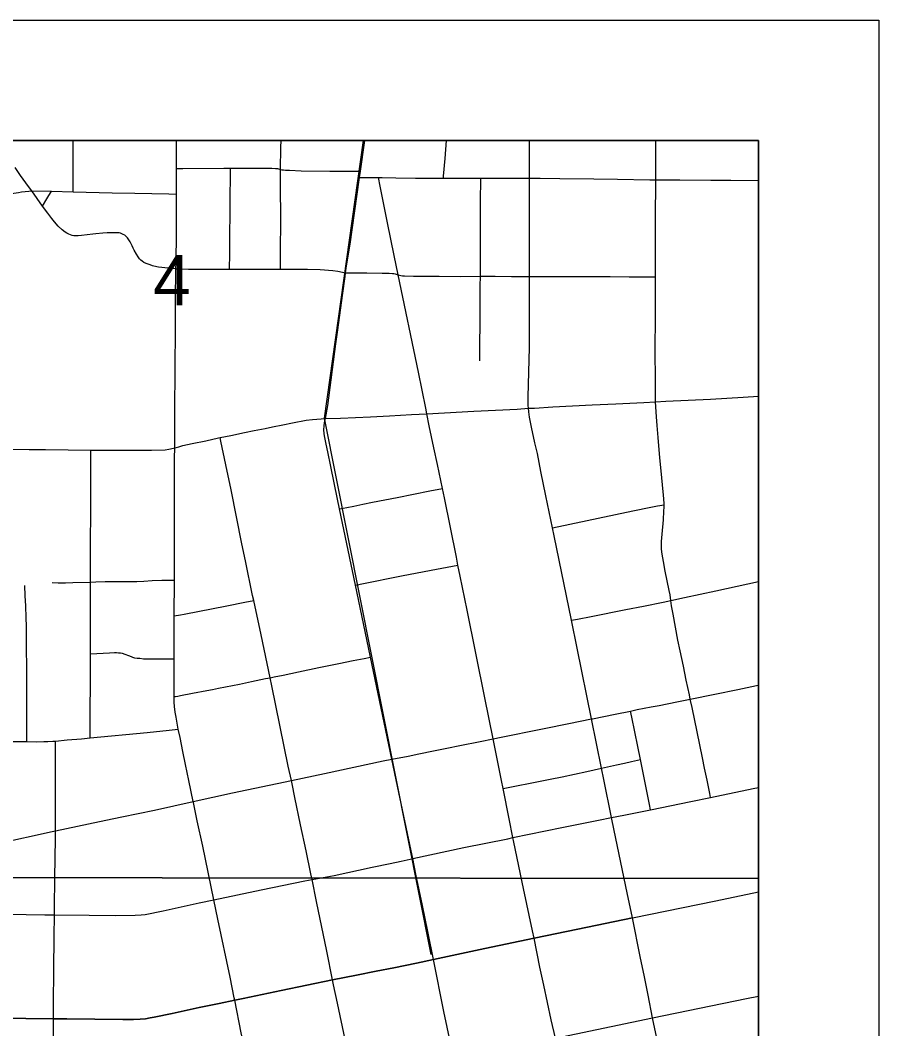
# Model space of a CAD drawing. Extents: x 0 to 34, y 0 to 22.
# Drawn here: x 8.286 to 9, y 20.161 to 21 of the extents above; entities that cross this region are included whole.
import ezdxf

# ---------------------------------------------------------------- set-up
doc = ezdxf.new("R2010")
doc.units = 0
for name, color, linetype in [('GM_X_City_Street', 7, 'Continuous'), ('GM_X_County_Road', 7, 'Continuous'), ('GM_X_Rail_Line', 7, 'Continuous'), ('GM_X_Section_Text', 7, 'Continuous'), ('GM_X_State_Route', 7, 'Continuous'), ('GM_X_Township_Road', 7, 'Continuous'), ('GM_X_Unincorporated', 7, 'Continuous'), ('SH_Data', 7, 'Continuous')]:
    doc.layers.add(name, color=color, linetype=linetype)

msp = doc.modelspace()

# ---------------------------------------------------------------- linework, layer by layer
at = {"layer": 'GM_X_City_Street'}
for points in [[(8.33031, 20.85723), (8.33032, 20.88691), (8.33032, 20.89996)], [(8.43013, 20.35007), (8.42648, 20.36751), (8.4237, 20.38082), (8.42151, 20.39169), (8.41914, 20.40339), (8.41768, 20.41038), (8.41669, 20.41511), (8.41578, 20.4201), (8.41501, 20.42446), (8.41446, 20.42904), (8.41431, 20.43279), (8.41429, 20.43736), (8.41418, 20.45868), (8.41419, 20.46877), (8.41419, 20.48821), (8.41426, 20.50453), (8.41438, 20.53424), (8.4144, 20.53833), (8.4144, 20.56296), (8.41454, 20.57978), (8.41454, 20.59348), (8.41462, 20.60812), (8.41455, 20.61864), (8.41462, 20.63566), (8.4149, 20.64422), (8.41489, 20.67671), (8.41496, 20.7077), (8.41531, 20.74537), (8.41538, 20.76696), (8.41573, 20.79312), (8.4158, 20.798), (8.41606, 20.82281), (8.41604, 20.84142), (8.41606, 20.85537), (8.41608, 20.86932), (8.41612, 20.8766), (8.41623, 20.89996)], [(8.50267, 20.87586), (8.50301, 20.89406), (8.50306, 20.89996)], [(8.63804, 20.86852), (8.63817, 20.8701), (8.63938, 20.88496), (8.6406, 20.89996)], [(8.86001, 20.35342), (8.85939, 20.35664), (8.85725, 20.36783), (8.85515, 20.37773), (8.85345, 20.38652), (8.84893, 20.40807), (8.84471, 20.42824), (8.84321, 20.43528), (8.8425, 20.43878), (8.83993, 20.45107), (8.8375, 20.46272), (8.83482, 20.4755), (8.83298, 20.48432), (8.82895, 20.50591), (8.82776, 20.51294), (8.82713, 20.51733), (8.82645, 20.52199), (8.8257, 20.52572), (8.82241, 20.54162), (8.82087, 20.54984), (8.81992, 20.55591), (8.81944, 20.55995), (8.8193, 20.56292), (8.8193, 20.56627), (8.81982, 20.57252), (8.82093, 20.58443), (8.82135, 20.59162), (8.82159, 20.59483), (8.82156, 20.59694), (8.82159, 20.59769), (8.82119, 20.60174), (8.82092, 20.60498), (8.82004, 20.61354), (8.81902, 20.62515), (8.81808, 20.63589), (8.81669, 20.65278), (8.81577, 20.6628), (8.81518, 20.67006), (8.81431, 20.68247), (8.81429, 20.68744), (8.81426, 20.6991), (8.81418, 20.72625), (8.81434, 20.75248), (8.8143, 20.78644), (8.81431, 20.80361), (8.81444, 20.8342), (8.81455, 20.86727), (8.81461, 20.87592), (8.81457, 20.89996)], [(8.41573, 20.79312), (8.40928, 20.79379), (8.40127, 20.79462), (8.39973, 20.79486), (8.39633, 20.79569), (8.39432, 20.79636), (8.39249, 20.797), (8.39095, 20.7976), (8.38913, 20.79851), (8.3877, 20.79947), (8.38661, 20.80042), (8.38551, 20.80158), (8.38422, 20.80323), (8.3829, 20.80538), (8.38102, 20.80862), (8.38018, 20.81034), (8.37918, 20.81239), (8.37763, 20.81554), (8.37713, 20.81653), (8.376, 20.81815), (8.37532, 20.81901), (8.37432, 20.82005), (8.37312, 20.82102), (8.37189, 20.82173), (8.37059, 20.82236), (8.36953, 20.82272), (8.36839, 20.823), (8.36735, 20.82312), (8.36515, 20.8232), (8.3631, 20.82316), (8.36122, 20.82315), (8.35864, 20.82301), (8.35502, 20.82273), (8.34915, 20.8222), (8.34663, 20.82194), (8.33726, 20.82093), (8.33433, 20.82061), (8.332, 20.82063), (8.3307, 20.82068), (8.32949, 20.82087), (8.328, 20.82135), (8.32661, 20.82189), (8.32512, 20.82274), (8.32363, 20.82359), (8.32107, 20.82551), (8.31783, 20.82875), (8.31463, 20.83233), (8.31242, 20.83508), (8.30909, 20.83938), (8.30486, 20.84535), (8.29586, 20.85805), (8.29316, 20.86148), (8.28647, 20.87073), (8.28211, 20.87732)], [(8.41612, 20.8766), (8.42149, 20.87662), (8.45547, 20.87675), (8.46118, 20.87677), (8.48635, 20.87687), (8.4953, 20.87677), (8.49848, 20.87664), (8.50021, 20.87647), (8.50165, 20.87612), (8.50267, 20.87586), (8.50378, 20.87559), (8.50503, 20.87534), (8.50684, 20.87516), (8.50998, 20.87508), (8.51985, 20.87468), (8.54363, 20.87442), (8.56164, 20.87447), (8.56904, 20.87449)], [(8.46026, 20.79286), (8.46052, 20.80574), (8.4606, 20.81165), (8.46049, 20.81469), (8.46118, 20.87677)], [(8.50266, 20.79278), (8.50263, 20.79616), (8.50257, 20.80269), (8.50251, 20.80968), (8.50276, 20.83152), (8.50251, 20.86546), (8.50265, 20.87437), (8.50267, 20.87586)], [(8.56826, 20.86902), (8.57654, 20.86902), (8.58408, 20.86901), (8.5872, 20.86901), (8.59854, 20.86884), (8.61495, 20.86867), (8.62799, 20.86867), (8.63804, 20.86852), (8.6395, 20.8685), (8.65438, 20.86849), (8.66915, 20.86863), (8.67232, 20.86866), (8.70963, 20.86849), (8.71836, 20.86848), (8.73494, 20.8683), (8.76304, 20.86796), (8.78267, 20.86779), (8.80958, 20.86727), (8.81455, 20.86727), (8.83446, 20.86727), (8.86036, 20.86692), (8.87711, 20.86675), (8.9, 20.86674)], [(8.6242, 20.67255), (8.6233, 20.67717), (8.61724, 20.70732), (8.60041, 20.78827), (8.59709, 20.80416), (8.59153, 20.8315), (8.58548, 20.86197), (8.58408, 20.86901)], [(8.66843, 20.71661), (8.66861, 20.7612), (8.66873, 20.77861), (8.66876, 20.78695), (8.66883, 20.79763), (8.66898, 20.82588), (8.66898, 20.85419), (8.66909, 20.86304), (8.66915, 20.86863)], [(8.24535, 20.84633), (8.24959, 20.84796), (8.25348, 20.84945), (8.2572, 20.85077), (8.25987, 20.8517), (8.26461, 20.85299), (8.26974, 20.85414), (8.27704, 20.85545), (8.28474, 20.8567), (8.28737, 20.85706), (8.29342, 20.85778), (8.29586, 20.85805)], [(8.29586, 20.85805), (8.31221, 20.85766), (8.33031, 20.85723), (8.36272, 20.85647), (8.38158, 20.85607), (8.40987, 20.8555), (8.41606, 20.85537)], [(8.30486, 20.84535), (8.30849, 20.85141), (8.31221, 20.85766)], [(8.41573, 20.79312), (8.42007, 20.79301), (8.42609, 20.79286), (8.46026, 20.79286), (8.46343, 20.79285), (8.50266, 20.79278), (8.52494, 20.79273), (8.53569, 20.79261), (8.54625, 20.79165), (8.55041, 20.79109), (8.55675, 20.78988)], [(8.55675, 20.78988), (8.56254, 20.78983), (8.57451, 20.78974), (8.58721, 20.78957), (8.59303, 20.78947), (8.5956, 20.78934), (8.59683, 20.78918), (8.59801, 20.7889), (8.60041, 20.78827), (8.60262, 20.78769), (8.60407, 20.78738), (8.60563, 20.78726), (8.61311, 20.78705), (8.63448, 20.78696), (8.65233, 20.78689), (8.66876, 20.78695), (8.68116, 20.78698), (8.69457, 20.78686), (8.70256, 20.78678), (8.70957, 20.78679), (8.71578, 20.78668), (8.74114, 20.78677), (8.75851, 20.78667), (8.77656, 20.78667), (8.79245, 20.78657), (8.81129, 20.78646), (8.8143, 20.78644)], [(8.71336, 20.23643), (8.71213, 20.2424), (8.70468, 20.27777), (8.69661, 20.3164), (8.69587, 20.32008), (8.69275, 20.33563), (8.68772, 20.36081), (8.68632, 20.36759), (8.67934, 20.4023), (8.6725, 20.43626), (8.65778, 20.50928), (8.65202, 20.53754), (8.65015, 20.54655), (8.64882, 20.55326), (8.63894, 20.60267), (8.63727, 20.61048), (8.63301, 20.63028), (8.63012, 20.64413), (8.62625, 20.66264), (8.6242, 20.67255)], [(8.54572, 20.20166), (8.541, 20.22551), (8.53252, 20.26685), (8.52884, 20.2853), (8.52789, 20.29003), (8.52387, 20.30914), (8.51928, 20.33071), (8.51454, 20.35348), (8.51231, 20.36465), (8.51174, 20.36748), (8.50909, 20.37934), (8.49531, 20.44628), (8.49391, 20.45299), (8.48645, 20.4887), (8.48031, 20.51725), (8.47942, 20.52137), (8.47356, 20.55015), (8.47055, 20.56429), (8.4615, 20.60942), (8.45715, 20.63018), (8.45313, 20.64984), (8.45253, 20.65279)], [(8.34451, 20.40294), (8.34435, 20.41884), (8.3447, 20.45509), (8.34467, 20.47287), (8.34459, 20.53128), (8.34458, 20.53255), (8.34471, 20.56077), (8.34487, 20.59509), (8.3449, 20.61659), (8.34491, 20.62157), (8.34494, 20.6386), (8.34494, 20.64226)], [(8.55175, 20.59346), (8.55771, 20.59468), (8.56347, 20.59586), (8.5711, 20.59742), (8.57922, 20.59908), (8.5996, 20.60307), (8.61308, 20.60571), (8.62666, 20.60836), (8.63727, 20.61048)], [(8.72869, 20.57772), (8.79549, 20.59178), (8.81039, 20.5949), (8.81591, 20.59591), (8.82156, 20.59694)], [(8.56497, 20.53009), (8.57175, 20.53145), (8.58136, 20.53338), (8.59212, 20.53554), (8.60332, 20.53779), (8.62779, 20.54243), (8.65015, 20.54655)], [(8.29164, 20.39987), (8.29168, 20.41339), (8.29174, 20.43325), (8.2918, 20.45598), (8.29142, 20.48327), (8.29142, 20.49581), (8.29117, 20.50288), (8.29081, 20.51281), (8.29043, 20.52113), (8.29021, 20.52977)], [(8.31284, 20.53227), (8.31773, 20.53208), (8.3238, 20.53203), (8.32985, 20.53214), (8.34458, 20.53255), (8.34922, 20.53291), (8.3569, 20.53307), (8.36218, 20.53302), (8.38321, 20.53314), (8.38903, 20.53326), (8.39593, 20.53378), (8.40405, 20.53429), (8.40909, 20.53426), (8.41438, 20.53424)], [(8.74451, 20.50082), (8.7494, 20.50174), (8.76101, 20.50395), (8.78982, 20.50967), (8.80438, 20.51261), (8.82084, 20.51599), (8.82713, 20.51733), (8.83848, 20.51966), (8.86454, 20.5252), (8.9, 20.53302)], [(8.41426, 20.50453), (8.41944, 20.50545), (8.42241, 20.50598), (8.45812, 20.51287), (8.47298, 20.51581), (8.48031, 20.51725)], [(8.34467, 20.47287), (8.36054, 20.47371), (8.36474, 20.47393), (8.3664, 20.47394), (8.36802, 20.47381), (8.3697, 20.47362), (8.37093, 20.47343), (8.37843, 20.47057), (8.3795, 20.47016), (8.38117, 20.46968), (8.38355, 20.46936), (8.38568, 20.46917), (8.38883, 20.46889), (8.39987, 20.46877), (8.40799, 20.46877), (8.41419, 20.46877)], [(8.41429, 20.43736), (8.41525, 20.43751), (8.41721, 20.43782), (8.41941, 20.43824), (8.42958, 20.44026), (8.44129, 20.44253), (8.44604, 20.44336), (8.4512, 20.44443), (8.46843, 20.44773), (8.47854, 20.44999), (8.49018, 20.45226), (8.49391, 20.45299), (8.49741, 20.45367), (8.50489, 20.4552), (8.51757, 20.45795), (8.53454, 20.46144), (8.55121, 20.4648), (8.56296, 20.46731), (8.57208, 20.46907), (8.57751, 20.47012)], [(8.81029, 20.34324), (8.80943, 20.3475), (8.8018, 20.38501), (8.7996, 20.39583), (8.79456, 20.42016), (8.79348, 20.42536)], [(8.27809, 20.3999), (8.29164, 20.39987), (8.29997, 20.39985), (8.30575, 20.39996), (8.30917, 20.39996), (8.31328, 20.40022), (8.31546, 20.40039), (8.32537, 20.40128), (8.33732, 20.4023), (8.34451, 20.40294), (8.39179, 20.40747), (8.41004, 20.40952), (8.41768, 20.41038)], [(8.31399, 20.1694), (8.31399, 20.17555), (8.314, 20.18176), (8.31426, 20.20999), (8.31436, 20.23753), (8.31465, 20.25583), (8.31474, 20.26163), (8.31502, 20.28648), (8.31559, 20.31934), (8.31564, 20.32565), (8.31569, 20.33153), (8.3155, 20.34604), (8.3157, 20.38513), (8.31551, 20.39676), (8.31546, 20.40039)], [(8.68772, 20.36081), (8.69743, 20.36278), (8.71167, 20.36561), (8.72691, 20.36865), (8.73667, 20.3706), (8.75718, 20.37508), (8.76951, 20.37777), (8.78198, 20.38048), (8.78864, 20.38193), (8.79437, 20.38327), (8.8018, 20.38501)], [(8.73114, 20.15326), (8.72754, 20.16859), (8.72144, 20.19739), (8.71832, 20.21226), (8.71336, 20.23643)], [(8.56262, 20.12181), (8.54997, 20.18237), (8.54663, 20.19753), (8.54572, 20.20166)], [(8.81194, 20.17023), (8.88991, 20.1861), (8.9, 20.18822)]]:
    msp.add_lwpolyline(points, dxfattribs=at)
at = {"layer": 'GM_X_County_Road'}
for p, q in [((8.56904, 20.87449), (8.57266, 20.89996)), ((8.56826, 20.86902), (8.56904, 20.87449)), ((8.56497, 20.53009), (8.55175, 20.59346)), ((8.59529, 20.38522), (8.57751, 20.47012)), ((8.76951, 20.37777), (8.76118, 20.4188)), ((8.45173, 20.18217), (8.46452, 20.18481)), ((8.73114, 20.15326), (8.81194, 20.17023))]:
    msp.add_line(p, q, dxfattribs=at)
for points in [[(8.70963, 20.86849), (8.70961, 20.87474), (8.70961, 20.88684), (8.70961, 20.89996)], [(8.55675, 20.78988), (8.55724, 20.79356), (8.5604, 20.81378), (8.56826, 20.86902)], [(8.70957, 20.78679), (8.7096, 20.80014), (8.7097, 20.81085), (8.70962, 20.84893), (8.70963, 20.86849)], [(8.53996, 20.66874), (8.54188, 20.67949), (8.54859, 20.73074), (8.55023, 20.74241), (8.55453, 20.773), (8.55634, 20.78675), (8.55675, 20.78988)], [(8.70869, 20.67711), (8.7086, 20.67938), (8.70862, 20.68222), (8.70862, 20.68666), (8.70956, 20.72783), (8.70952, 20.7604), (8.70956, 20.77789), (8.70957, 20.78583), (8.70957, 20.78679)], [(8.72869, 20.57772), (8.72315, 20.60433), (8.71909, 20.62457), (8.71632, 20.63956), (8.71399, 20.64854), (8.7114, 20.66144), (8.70973, 20.66978), (8.70901, 20.67409), (8.70869, 20.67711)], [(8.55175, 20.59346), (8.55006, 20.60154), (8.54442, 20.62863), (8.54184, 20.64101), (8.54054, 20.64722), (8.53944, 20.65279), (8.53891, 20.65586), (8.53868, 20.65951), (8.53886, 20.66241), (8.53927, 20.66543), (8.53996, 20.66874)], [(8.74451, 20.50082), (8.73009, 20.57101), (8.72869, 20.57772)], [(8.57751, 20.47012), (8.57024, 20.50478), (8.56497, 20.53009)], [(8.76118, 20.4188), (8.74925, 20.47758), (8.74451, 20.50082)], [(8.84321, 20.43528), (8.86375, 20.43939), (8.88271, 20.44334), (8.89841, 20.44659), (8.9, 20.44692)], [(8.79348, 20.42536), (8.79911, 20.42653), (8.81086, 20.42879), (8.81731, 20.43), (8.8322, 20.43304), (8.84321, 20.43528)], [(8.76118, 20.4188), (8.76209, 20.41897), (8.78076, 20.42273), (8.79348, 20.42536)], [(8.67934, 20.4023), (8.6861, 20.40364), (8.69587, 20.40562), (8.70944, 20.4083), (8.72189, 20.41071), (8.74239, 20.41495), (8.76118, 20.4188)], [(8.59529, 20.38522), (8.60887, 20.38782), (8.61768, 20.38977), (8.62974, 20.39222), (8.64098, 20.39446), (8.65173, 20.39658), (8.66871, 20.40011), (8.67934, 20.4023)], [(8.51174, 20.36748), (8.53931, 20.37326), (8.58801, 20.3839), (8.59529, 20.38522)], [(8.6125, 20.3027), (8.61117, 20.30908), (8.60001, 20.36276), (8.59529, 20.38522)], [(8.77785, 20.33677), (8.77141, 20.36843), (8.76951, 20.37777)], [(8.43013, 20.35007), (8.46272, 20.35721), (8.51174, 20.36748)], [(8.86001, 20.35342), (8.89559, 20.36093), (8.9, 20.36186)], [(8.81029, 20.34324), (8.84362, 20.34997), (8.86001, 20.35342)], [(8.31564, 20.32565), (8.35202, 20.33355), (8.36415, 20.33601), (8.37085, 20.33727), (8.39781, 20.343), (8.43013, 20.35007)], [(8.44721, 20.26831), (8.43798, 20.31285), (8.43345, 20.3341), (8.43029, 20.34929), (8.43013, 20.35007)], [(8.69587, 20.32008), (8.73636, 20.32845), (8.7669, 20.33465), (8.77785, 20.33677)], [(8.77785, 20.33677), (8.78796, 20.33873), (8.81029, 20.34324)], [(8.79527, 20.25346), (8.79087, 20.27424), (8.78004, 20.32583), (8.77785, 20.33677)], [(8.20969, 20.30288), (8.21616, 20.30422), (8.26742, 20.31518), (8.31271, 20.32502), (8.31564, 20.32565)], [(8.6125, 20.3027), (8.65505, 20.3117), (8.69166, 20.31917), (8.69587, 20.32008)], [(8.52884, 20.2853), (8.54724, 20.28864), (8.57893, 20.29551), (8.59389, 20.2986), (8.60302, 20.30051), (8.61049, 20.30221), (8.6125, 20.3027)], [(8.62971, 20.21855), (8.62499, 20.24208), (8.62066, 20.26346), (8.61523, 20.28957), (8.6125, 20.3027)], [(8.44721, 20.26831), (8.48663, 20.27663), (8.52293, 20.28423), (8.52884, 20.2853)], [(8.79527, 20.25346), (8.8645, 20.26743), (8.9, 20.27487)], [(8.31465, 20.25583), (8.34368, 20.25543), (8.36537, 20.25522), (8.38175, 20.25545), (8.38667, 20.25577), (8.39003, 20.2562), (8.40512, 20.25914), (8.43507, 20.26574), (8.44721, 20.26831)], [(8.46452, 20.18481), (8.46411, 20.18682), (8.46067, 20.20384), (8.45055, 20.25217), (8.44721, 20.26831)], [(8.14257, 20.25707), (8.14758, 20.25709), (8.17223, 20.25716), (8.2124, 20.25683), (8.24485, 20.25661), (8.27562, 20.25635), (8.30662, 20.25593), (8.31465, 20.25583)], [(8.71336, 20.23643), (8.74978, 20.24399), (8.79527, 20.25346)], [(8.62971, 20.21855), (8.67255, 20.22796), (8.71336, 20.23643)], [(8.54572, 20.20166), (8.56572, 20.20577), (8.58217, 20.20888), (8.59689, 20.21177), (8.61569, 20.21559), (8.62971, 20.21855)], [(8.64675, 20.13558), (8.64577, 20.14013), (8.63846, 20.17542), (8.62971, 20.21855)], [(8.46452, 20.18481), (8.47171, 20.1863), (8.50308, 20.19289), (8.54572, 20.20166)], [(8.31399, 20.1694), (8.32505, 20.16925), (8.37153, 20.16876), (8.38051, 20.16883), (8.38582, 20.16896), (8.39044, 20.16944), (8.3944, 20.17005), (8.39759, 20.17073), (8.4125, 20.17386), (8.43501, 20.17872), (8.45173, 20.18217)], [(8.4818, 20.10167), (8.47535, 20.13279), (8.46991, 20.15772), (8.46452, 20.18481)], [(8.25454, 20.07875), (8.26505, 20.08873), (8.30472, 20.1262), (8.30612, 20.12772), (8.30764, 20.12933), (8.30915, 20.13101), (8.31007, 20.13236), (8.31083, 20.1336), (8.31153, 20.13479), (8.31212, 20.13609), (8.31272, 20.1377), (8.31315, 20.13937), (8.31342, 20.14154), (8.31364, 20.1437), (8.31369, 20.14564), (8.3138, 20.14737), (8.31374, 20.15083), (8.31379, 20.15482), (8.31399, 20.1694)], [(8.25603, 20.17457), (8.25817, 20.17341), (8.26112, 20.17212), (8.26449, 20.17096), (8.26754, 20.17028), (8.27136, 20.16988), (8.29082, 20.16973), (8.31399, 20.1694)]]:
    msp.add_lwpolyline(points, dxfattribs=at)
at = {"layer": 'GM_X_Rail_Line'}
msp.add_lwpolyline([(8.57139, 20.89996), (8.53897, 20.66884), (8.62772, 20.22287)], dxfattribs=at)
at = {"layer": 'GM_X_State_Route'}
msp.add_line((8.46452, 20.18481), (8.45173, 20.18217), dxfattribs=at)
for points in [[(8.9, 19.05919), (8.9, 20.89996), (6.88573, 20.89996)], [(8.79527, 20.25346), (8.74978, 20.24399), (8.71336, 20.23643)], [(8.83601, 19.91254), (8.83597, 19.91666), (8.83581, 19.92344), (8.83565, 19.92703), (8.83193, 20.00245), (8.82983, 20.05801), (8.82799, 20.08801), (8.82793, 20.08901), (8.82741, 20.0936), (8.82685, 20.09831), (8.82581, 20.10433), (8.82497, 20.10867), (8.82204, 20.12219), (8.81194, 20.17023), (8.80825, 20.18912), (8.80509, 20.20424), (8.80158, 20.22103), (8.79527, 20.25346)], [(8.71336, 20.23643), (8.67255, 20.22796), (8.62971, 20.21855)], [(8.62971, 20.21855), (8.61569, 20.21559), (8.59689, 20.21177), (8.58217, 20.20888), (8.56572, 20.20577), (8.54572, 20.20166)], [(8.54572, 20.20166), (8.50308, 20.19289), (8.47171, 20.1863), (8.46452, 20.18481)], [(8.45173, 20.18217), (8.43501, 20.17872), (8.4125, 20.17386), (8.39759, 20.17073), (8.3944, 20.17005), (8.39044, 20.16944), (8.38582, 20.16896), (8.38051, 20.16883), (8.37153, 20.16876), (8.32505, 20.16925), (8.31399, 20.1694)], [(8.31399, 20.1694), (8.29082, 20.16973), (8.27136, 20.16988), (8.26754, 20.17028), (8.26449, 20.17096), (8.26112, 20.17212), (8.25817, 20.17341), (8.25603, 20.17457)]]:
    msp.add_lwpolyline(points, dxfattribs=at)
at = {"layer": 'GM_X_Township_Road'}
msp.add_line((8.88729, 20.68641), (8.9, 20.68714), dxfattribs=at)
for points in [[(8.9, 17.26338), (8.9, 20.89996), (5.78179, 20.89996)], [(8.70869, 20.67711), (8.71382, 20.67738), (8.7291, 20.67835), (8.76176, 20.67993), (8.78148, 20.68084), (8.80454, 20.68194), (8.81431, 20.68247)], [(8.81431, 20.68247), (8.82307, 20.68294), (8.85998, 20.68485), (8.88729, 20.68641)], [(8.53996, 20.66874), (8.5525, 20.66884), (8.57751, 20.67005), (8.59322, 20.67074), (8.61155, 20.67184), (8.6242, 20.67255)], [(8.6242, 20.67255), (8.63906, 20.67337), (8.66324, 20.67461), (8.69936, 20.67655), (8.70869, 20.67711)], [(8.45253, 20.65279), (8.46145, 20.6546), (8.4726, 20.6569), (8.48086, 20.65853), (8.48978, 20.66032), (8.49603, 20.66158), (8.50451, 20.66336), (8.51269, 20.665), (8.52385, 20.66715), (8.52916, 20.66787), (8.53996, 20.66874)], [(8.4149, 20.64422), (8.41816, 20.64516), (8.42151, 20.64606), (8.42925, 20.64784), (8.44055, 20.65014), (8.45113, 20.6525), (8.45253, 20.65279)], [(8.22036, 20.64359), (8.22445, 20.64357), (8.24519, 20.64342), (8.26091, 20.64326), (8.29363, 20.64297), (8.30735, 20.64273), (8.34494, 20.64226)], [(8.34494, 20.64226), (8.36254, 20.64221), (8.39526, 20.64227), (8.40679, 20.64257), (8.40984, 20.64301), (8.41356, 20.6439), (8.4149, 20.64422)]]:
    msp.add_lwpolyline(points, dxfattribs=at)
at = {"layer": 'GM_X_Unincorporated'}
for points in [[(8.9, 20.28618), (8.9, 20.89996), (7.91044, 20.89996), (7.90836, 20.28708)], [(8.9, 19.27567), (8.9, 20.28618), (7.90836, 20.28708), (7.90787, 19.27209)]]:
    msp.add_lwpolyline(points, close=True, dxfattribs=at)
at = {"layer": 'SH_Data'}
for p, q in [((2, 20.99996), (9, 20.99996)), ((9, 20.99996), (9, 13.99996)), ((2.1, 20.89996), (8.9, 20.89996)), ((8.9, 20.89996), (8.9, 14.09996))]:
    msp.add_line(p, q, dxfattribs=at)

# ---------------------------------------------------------------- texts
at = {"layer": 'GM_X_Section_Text'}
msp.add_text('4', height=0.04186, rotation=0.00001, dxfattribs=at).set_placement((8.39681, 20.76266))

doc.saveas('drawing.dxf')
